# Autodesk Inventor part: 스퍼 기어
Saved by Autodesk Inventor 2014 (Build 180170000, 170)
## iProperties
Created: 2026-06
Part Number: 스퍼 기어
Material: 일반
Document SubType Name: Modeling
Designer: dg
Density: 1 g/cm^3
Appearance: 기본값
Author: dg
Author: jhkim
Creation Date: 2026-05-29
Sending System: Autodesk Inventor 2027
Preprocessor: ST-DEVELOPER v20.1
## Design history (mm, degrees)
node "스퍼 기어1"
node "솔리드1"
node "기준1"
